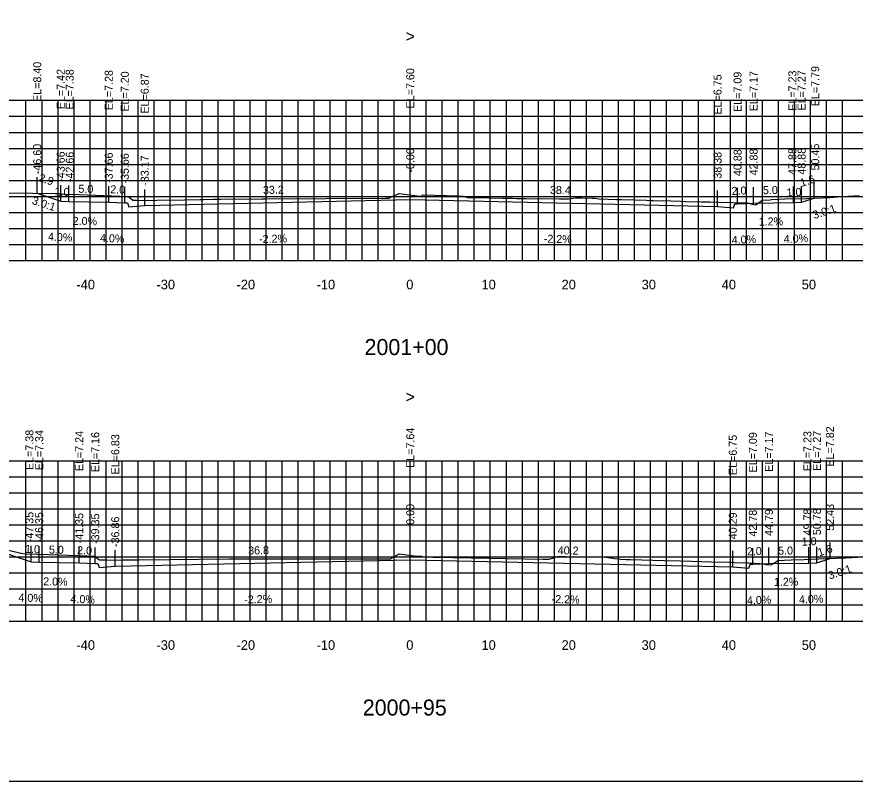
# Model space of a CAD drawing. Extents: x 1800876 to 1802446, y 250079 to 250269.
# Drawn here: x 1802241.8 to 1802346.6, y 250079.4 to 250174.9 of the extents above; entities that cross this region are included whole.
import ezdxf

# ---------------------------------------------------------------- set-up
doc = ezdxf.new("R2010")
doc.units = 0
for name, color, linetype in [('1', 7, 'Continuous'), ('10', 7, 'Continuous'), ('3', 7, 'Continuous'), ('4', 7, 'Continuous'), ('60', 7, 'Continuous'), ('CL-CNST', 7, 'Continuous'), ('Level 62', 7, 'Continuous'), ('M-ROADS', 7, 'Continuous')]:
    doc.layers.add(name, color=color, linetype=linetype)

msp = doc.modelspace()

# ---------------------------------------------------------------- linework, layer by layer
for p, q in [((1802244.4, 250152.83), (1802244.4, 250154.83)), ((1802247.34, 250151.85), (1802247.34, 250153.85)), ((1802248.34, 250151.81), (1802248.34, 250153.81)), ((1802253.34, 250151.71), (1802253.34, 250153.71)), ((1802291, 250152.03), (1802291, 250154.03)), ((1802338.88, 250151.66), (1802338.88, 250153.66)), ((1802339.88, 250151.7), (1802339.88, 250153.7)), ((1802341.46, 250152.23), (1802341.46, 250154.23)), ((1802255.34, 250151.63), (1802255.34, 250153.63)), ((1802257.83, 250151.3), (1802257.83, 250153.3)), ((1802329.38, 250151.19), (1802329.38, 250153.19)), ((1802331.88, 250151.52), (1802331.88, 250153.52)), ((1802333.88, 250151.6), (1802333.88, 250153.6)), ((1802243.65, 250106.82), (1802243.65, 250108.82)), ((1802244.65, 250106.78), (1802244.65, 250108.78)), ((1802244.65, 250106.78), (1802244.65, 250108.78)), ((1802249.65, 250106.68), (1802249.65, 250108.68)), ((1802291, 250107.07), (1802291, 250109.07)), ((1802340.78, 250106.66), (1802340.78, 250108.66)), ((1802340.79, 250106.66), (1802340.79, 250108.66)), ((1802341.78, 250106.7), (1802341.78, 250108.7)), ((1802341.79, 250106.7), (1802341.79, 250108.7)), ((1802343.43, 250107.25), (1802343.43, 250109.25)), ((1802251.65, 250106.6), (1802251.65, 250108.6)), ((1802251.65, 250106.6), (1802251.65, 250108.6)), ((1802254.14, 250106.26), (1802254.14, 250108.26)), ((1802254.15, 250106.26), (1802254.15, 250108.26)), ((1802331.29, 250106.19), (1802331.29, 250108.19)), ((1802331.29, 250106.19), (1802331.29, 250108.19)), ((1802333.78, 250106.52), (1802333.78, 250108.52)), ((1802333.79, 250106.52), (1802333.79, 250108.52)), ((1802335.78, 250106.6), (1802335.78, 250108.6)), ((1802335.79, 250106.6), (1802335.79, 250108.6))]:
    msp.add_line(p, q)
msp.add_lwpolyline([(1802141, 250079.43), (1802441, 250079.43), (1802441, 250269.43), (1802141, 250269.43)], close=True)
at = {"layer": '60'}
for p, q in [((1802141, 250144.43), (1802441, 250144.43)), ((1802251, 250144.37), (1802251, 250144.43)), ((1802261, 250144.37), (1802261, 250144.43)), ((1802271, 250144.37), (1802271, 250144.43)), ((1802281, 250144.37), (1802281, 250144.43)), ((1802291, 250144.37), (1802291, 250144.43)), ((1802301, 250144.37), (1802301, 250144.43)), ((1802311, 250144.37), (1802311, 250144.43)), ((1802321, 250144.37), (1802321, 250144.43)), ((1802331, 250144.37), (1802331, 250144.43)), ((1802341, 250144.37), (1802341, 250144.43)), ((1802141, 250099.43), (1802441, 250099.43)), ((1802251, 250099.37), (1802251, 250099.43)), ((1802261, 250099.37), (1802261, 250099.43)), ((1802271, 250099.37), (1802271, 250099.43)), ((1802281, 250099.37), (1802281, 250099.43)), ((1802291, 250099.37), (1802291, 250099.43)), ((1802301, 250099.37), (1802301, 250099.43)), ((1802311, 250099.37), (1802311, 250099.43)), ((1802321, 250099.37), (1802321, 250099.43)), ((1802331, 250099.37), (1802331, 250099.43)), ((1802341, 250099.37), (1802341, 250099.43))]:
    msp.add_line(p, q, dxfattribs=at)
at = {"layer": 'CL-CNST'}
for points in [[(1802244.4, 250152.83), (1802247.34, 250151.85), (1802248.34, 250151.81), (1802253.34, 250151.71), (1802255.34, 250151.63), (1802255.67, 250151.63), (1802255.83, 250151.13), (1802257.83, 250151.3), (1802291, 250152.03), (1802329.38, 250151.19), (1802331.38, 250151.02), (1802331.55, 250151.52), (1802331.88, 250151.52), (1802333.88, 250151.6), (1802338.88, 250151.66), (1802339.88, 250151.7), (1802341.46, 250152.23)], [(1802239.14, 250108.32), (1802243.65, 250106.82), (1802243.65, 250106.82), (1802244.65, 250106.78), (1802244.65, 250106.78), (1802249.65, 250106.68), (1802249.65, 250106.68), (1802251.65, 250106.6), (1802251.65, 250106.6), (1802251.98, 250106.6), (1802251.98, 250106.6), (1802252.15, 250106.1), (1802252.15, 250106.1), (1802254.14, 250106.26), (1802254.15, 250106.26), (1802290.99, 250107.07), (1802291, 250107.07), (1802291.04, 250107.07), (1802331.29, 250106.19), (1802331.29, 250106.19), (1802333.29, 250106.02), (1802333.29, 250106.02), (1802333.45, 250106.52), (1802333.45, 250106.52), (1802333.78, 250106.52), (1802333.79, 250106.52), (1802335.78, 250106.6), (1802335.79, 250106.6), (1802340.78, 250106.66), (1802340.79, 250106.66), (1802341.78, 250106.7), (1802341.79, 250106.7), (1802343.43, 250107.25)]]:
    msp.add_lwpolyline(points, dxfattribs=at)
at = {"layer": 'Level 62'}
for p, q in [((1802141, 250164.43), (1802441, 250164.43)), ((1802243, 250144.43), (1802243, 250164.43)), ((1802245, 250144.43), (1802245, 250164.43)), ((1802247, 250144.43), (1802247, 250164.43)), ((1802249, 250144.43), (1802249, 250164.43)), ((1802251, 250144.43), (1802251, 250164.43)), ((1802253, 250144.43), (1802253, 250164.43)), ((1802255, 250144.43), (1802255, 250164.43)), ((1802257, 250144.43), (1802257, 250164.43)), ((1802259, 250144.43), (1802259, 250164.43)), ((1802261, 250144.43), (1802261, 250164.43)), ((1802263, 250144.43), (1802263, 250164.43)), ((1802265, 250144.43), (1802265, 250164.43)), ((1802267, 250144.43), (1802267, 250164.43)), ((1802269, 250144.43), (1802269, 250164.43)), ((1802271, 250144.43), (1802271, 250164.43)), ((1802273, 250144.43), (1802273, 250164.43)), ((1802275, 250144.43), (1802275, 250164.43)), ((1802277, 250144.43), (1802277, 250164.43)), ((1802279, 250144.43), (1802279, 250164.43)), ((1802281, 250144.43), (1802281, 250164.43)), ((1802283, 250144.43), (1802283, 250164.43)), ((1802285, 250144.43), (1802285, 250164.43)), ((1802287, 250144.43), (1802287, 250164.43)), ((1802289, 250144.43), (1802289, 250164.43)), ((1802291, 250144.43), (1802291, 250164.43)), ((1802293, 250144.43), (1802293, 250164.43)), ((1802295, 250144.43), (1802295, 250164.43)), ((1802297, 250144.43), (1802297, 250164.43)), ((1802299, 250144.43), (1802299, 250164.43)), ((1802301, 250144.43), (1802301, 250164.43)), ((1802303, 250144.43), (1802303, 250164.43)), ((1802305, 250144.43), (1802305, 250164.43)), ((1802307, 250144.43), (1802307, 250164.43)), ((1802309, 250144.43), (1802309, 250164.43)), ((1802311, 250144.43), (1802311, 250164.43)), ((1802313, 250144.43), (1802313, 250164.43)), ((1802315, 250144.43), (1802315, 250164.43)), ((1802317, 250144.43), (1802317, 250164.43)), ((1802319, 250144.43), (1802319, 250164.43)), ((1802321, 250144.43), (1802321, 250164.43)), ((1802323, 250144.43), (1802323, 250164.43)), ((1802325, 250144.43), (1802325, 250164.43)), ((1802327, 250144.43), (1802327, 250164.43)), ((1802329, 250144.43), (1802329, 250164.43)), ((1802331, 250144.43), (1802331, 250164.43)), ((1802333, 250144.43), (1802333, 250164.43)), ((1802335, 250144.43), (1802335, 250164.43)), ((1802337, 250144.43), (1802337, 250164.43)), ((1802339, 250144.43), (1802339, 250164.43)), ((1802341, 250144.43), (1802341, 250164.43)), ((1802343, 250144.43), (1802343, 250164.43)), ((1802345, 250144.43), (1802345, 250164.43)), ((1802141, 250162.43), (1802441, 250162.43)), ((1802141, 250160.43), (1802441, 250160.43)), ((1802141, 250158.43), (1802441, 250158.43)), ((1802141, 250156.43), (1802441, 250156.43)), ((1802141, 250154.43), (1802441, 250154.43)), ((1802141, 250152.43), (1802441, 250152.43)), ((1802141, 250150.43), (1802441, 250150.43)), ((1802141, 250148.43), (1802441, 250148.43)), ((1802141, 250146.43), (1802441, 250146.43)), ((1802141, 250144.43), (1802441, 250144.43)), ((1802141, 250119.43), (1802441, 250119.43)), ((1802243, 250099.43), (1802243, 250119.43)), ((1802245, 250099.43), (1802245, 250119.43)), ((1802247, 250099.43), (1802247, 250119.43)), ((1802249, 250099.43), (1802249, 250119.43)), ((1802251, 250099.43), (1802251, 250119.43)), ((1802253, 250099.43), (1802253, 250119.43)), ((1802255, 250099.43), (1802255, 250119.43)), ((1802257, 250099.43), (1802257, 250119.43)), ((1802259, 250099.43), (1802259, 250119.43)), ((1802261, 250099.43), (1802261, 250119.43)), ((1802263, 250099.43), (1802263, 250119.43)), ((1802265, 250099.43), (1802265, 250119.43)), ((1802267, 250099.43), (1802267, 250119.43)), ((1802269, 250099.43), (1802269, 250119.43)), ((1802271, 250099.43), (1802271, 250119.43)), ((1802273, 250099.43), (1802273, 250119.43)), ((1802275, 250099.43), (1802275, 250119.43)), ((1802277, 250099.43), (1802277, 250119.43)), ((1802279, 250099.43), (1802279, 250119.43)), ((1802281, 250099.43), (1802281, 250119.43)), ((1802283, 250099.43), (1802283, 250119.43)), ((1802285, 250099.43), (1802285, 250119.43)), ((1802287, 250099.43), (1802287, 250119.43)), ((1802289, 250099.43), (1802289, 250119.43)), ((1802291, 250099.43), (1802291, 250119.43)), ((1802293, 250099.43), (1802293, 250119.43)), ((1802295, 250099.43), (1802295, 250119.43)), ((1802297, 250099.43), (1802297, 250119.43)), ((1802299, 250099.43), (1802299, 250119.43)), ((1802301, 250099.43), (1802301, 250119.43)), ((1802303, 250099.43), (1802303, 250119.43)), ((1802305, 250099.43), (1802305, 250119.43)), ((1802307, 250099.43), (1802307, 250119.43)), ((1802309, 250099.43), (1802309, 250119.43)), ((1802311, 250099.43), (1802311, 250119.43)), ((1802313, 250099.43), (1802313, 250119.43)), ((1802315, 250099.43), (1802315, 250119.43)), ((1802317, 250099.43), (1802317, 250119.43)), ((1802319, 250099.43), (1802319, 250119.43)), ((1802321, 250099.43), (1802321, 250119.43)), ((1802323, 250099.43), (1802323, 250119.43)), ((1802325, 250099.43), (1802325, 250119.43)), ((1802327, 250099.43), (1802327, 250119.43)), ((1802329, 250099.43), (1802329, 250119.43)), ((1802331, 250099.43), (1802331, 250119.43)), ((1802333, 250099.43), (1802333, 250119.43)), ((1802335, 250099.43), (1802335, 250119.43)), ((1802337, 250099.43), (1802337, 250119.43)), ((1802339, 250099.43), (1802339, 250119.43)), ((1802341, 250099.43), (1802341, 250119.43)), ((1802343, 250099.43), (1802343, 250119.43)), ((1802345, 250099.43), (1802345, 250119.43)), ((1802141, 250117.43), (1802441, 250117.43)), ((1802141, 250115.43), (1802441, 250115.43)), ((1802141, 250113.43), (1802441, 250113.43)), ((1802141, 250111.43), (1802441, 250111.43)), ((1802141, 250109.43), (1802441, 250109.43)), ((1802141, 250107.43), (1802441, 250107.43)), ((1802141, 250105.43), (1802441, 250105.43)), ((1802141, 250103.43), (1802441, 250103.43)), ((1802141, 250101.43), (1802441, 250101.43)), ((1802141, 250099.43), (1802441, 250099.43))]:
    msp.add_line(p, q, dxfattribs=at)
at = {"layer": 'M-ROADS'}
for points in [[(1802233.84, 250152.97), (1802247.14, 250152.8), (1802247.71, 250152.72), (1802249.61, 250152.65), (1802255.77, 250152.44), (1802255.88, 250152.35), (1802256.35, 250151.98), (1802256.82, 250151.97), (1802257.82, 250151.94), (1802259.35, 250151.97), (1802262.8, 250152.02), (1802264.76, 250152.05), (1802265.16, 250152.05), (1802266.42, 250152.07), (1802267.29, 250152.08), (1802272.41, 250152.14), (1802272.58, 250152.14), (1802272.96, 250152.14), (1802287.91, 250152.21), (1802288.31, 250152.22), (1802288.46, 250152.3), (1802289.62, 250152.78), (1802291.92, 250152.49), (1802292.36, 250152.45), (1802292.37, 250152.44), (1802292.39, 250152.42), (1802292.47, 250152.57), (1802292.52, 250152.63), (1802296.98, 250152.49), (1802297.56, 250152.47), (1802298.2, 250152.31), (1802298.54, 250152.3), (1802298.96, 250152.29), (1802299.08, 250152.28), (1802299.15, 250152.28), (1802302.54, 250152.22), (1802303.25, 250152.21), (1802303.75, 250152.2), (1802304.31, 250152.19), (1802305.49, 250152.18), (1802309.6, 250152.13), (1802310.79, 250152.12), (1802311.67, 250152.26), (1802312.01, 250152.26), (1802312.43, 250152.25), (1802313.71, 250152.23), (1802314.05, 250152.2), (1802314.07, 250152.2), (1802314.55, 250152.12), (1802316.77, 250152.06), (1802316.8, 250152.06), (1802317.25, 250152.04), (1802317.44, 250152.04), (1802320.51, 250151.95), (1802321.04, 250151.93), (1802321.34, 250151.92), (1802323.53, 250151.86), (1802324.75, 250151.82), (1802325.41, 250151.81), (1802327.36, 250151.77), (1802327.39, 250151.77), (1802328.43, 250151.74), (1802329.51, 250151.72), (1802333.13, 250151.61), (1802333.27, 250151.58), (1802333.55, 250151.51), (1802334.15, 250151.4), (1802334.62, 250151.73), (1802334.94, 250151.96), (1802335.95, 250152.02), (1802336.12, 250152.03), (1802337.78, 250152.12), (1802340.53, 250152.19), (1802343.44, 250152.31), (1802344.35, 250152.37), (1802345.69, 250152.45), (1802347.08, 250152.54)], [(1802240.49, 250108.34), (1802242.37, 250107.89), (1802242.44, 250107.89), (1802242.89, 250107.81), (1802245.9, 250107.72), (1802250.63, 250107.56), (1802251.56, 250107.53), (1802252.07, 250107.14), (1802252.16, 250107.07), (1802253.11, 250107.05), (1802254.05, 250107.04), (1802255.13, 250107.05), (1802257.14, 250107.06), (1802268.34, 250107.2), (1802269.99, 250107.2), (1802270.23, 250107.2), (1802270.64, 250107.19), (1802270.91, 250107.18), (1802271.25, 250107.18), (1802271.48, 250107.19), (1802271.78, 250107.2), (1802285.27, 250107.2), (1802286.86, 250107.19), (1802288.5, 250107.18), (1802288.52, 250107.2), (1802288.8, 250107.35), (1802289.63, 250107.82), (1802291.76, 250107.54), (1802292.46, 250107.54), (1802292.48, 250107.5), (1802292.5, 250107.45), (1802293.36, 250107.43), (1802293.86, 250107.42), (1802294.16, 250107.42), (1802307.54, 250107.16), (1802308.36, 250107.15), (1802309.01, 250107.35), (1802309.25, 250107.43), (1802309.31, 250107.45), (1802309.33, 250107.46), (1802309.35, 250107.46), (1802309.36, 250107.46), (1802309.37, 250107.47), (1802309.37, 250107.47), (1802309.4, 250107.48), (1802310.01, 250107.47), (1802310.49, 250107.47), (1802315.24, 250107.45), (1802316.51, 250107.24), (1802317.29, 250107.14), (1802317.97, 250107.12), (1802318.08, 250107.12), (1802318.14, 250107.12), (1802318.31, 250107.11), (1802318.41, 250107.11), (1802318.52, 250107.11), (1802322.72, 250107), (1802324.71, 250106.94), (1802326.13, 250106.9), (1802328.62, 250106.83), (1802330.89, 250106.76), (1802331.55, 250106.74), (1802333.18, 250106.68), (1802333.34, 250106.68), (1802334.64, 250106.63), (1802335.29, 250106.53), (1802335.47, 250106.5), (1802335.74, 250106.47), (1802336.07, 250106.44), (1802336.35, 250106.63), (1802336.9, 250106.98), (1802337.72, 250107.03), (1802338.57, 250107.05), (1802340.21, 250107.12), (1802342, 250107.19), (1802344.22, 250107.28), (1802344.78, 250107.3), (1802345.39, 250107.33), (1802346.85, 250107.42)]]:
    msp.add_lwpolyline(points, dxfattribs=at)

# ---------------------------------------------------------------- texts
for rotation, p in [(341.5651, (1802243.68, 250151.51)), (18.4349, (1802341.46, 250149.59)), (18.4345, (1802343.4, 250104.6))]:
    msp.add_text('3.0:1', height=1, rotation=rotation).set_placement(p)
at = {"layer": '1'}
for s, p in [('2001+00', (1802285.29, 250132.63)), ('2000+95', (1802285.07, 250087.63))]:
    msp.add_text(s, height=2, dxfattribs=at).set_placement(p)
at = {"layer": '10'}
for s, p in [('-40', (1802249.3, 250140.83)), ('-30', (1802259.3, 250140.83)), ('-20', (1802269.3, 250140.83)), ('-10', (1802279.3, 250140.83)), ('0', (1802290.5, 250140.83)), ('10', (1802299.9, 250140.83)), ('20', (1802309.9, 250140.83)), ('30', (1802319.9, 250140.83)), ('40', (1802329.9, 250140.83)), ('50', (1802339.9, 250140.83)), ('-40', (1802249.3, 250095.83)), ('-30', (1802259.3, 250095.83)), ('-20', (1802269.3, 250095.83)), ('-10', (1802279.3, 250095.83)), ('0', (1802290.5, 250095.83)), ('10', (1802299.9, 250095.83)), ('20', (1802309.9, 250095.83)), ('30', (1802319.9, 250095.83)), ('40', (1802329.9, 250095.83)), ('50', (1802339.9, 250095.83))]:
    msp.add_text(s, height=1.2, dxfattribs=at).set_placement(p)
at = {"layer": '3'}
for s, p in [('EL=8.40', (1802244.9, 250164.22)), ('EL=7.60', (1802291.5, 250163.42)), ('EL=7.79', (1802342.08, 250163.69)), ('EL=7.42', (1802247.84, 250163.32)), ('EL=7.38', (1802248.96, 250163.28)), ('EL=7.28', (1802253.84, 250163.18)), ('EL=7.20', (1802255.84, 250163.02)), ('EL=6.87', (1802258.33, 250162.77)), ('EL=6.75', (1802329.88, 250162.65)), ('EL=7.09', (1802332.38, 250162.98)), ('EL=7.17', (1802334.38, 250163.06)), ('EL=7.23', (1802339.23, 250163.12)), ('EL=7.27', (1802340.38, 250163.16)), ('-46.60', (1802244.9, 250155.21)), ('50.45', (1802342.08, 250155.67)), ('-43.66', (1802247.84, 250154.26)), ('-42.66', (1802248.96, 250154.22)), ('-37.66', (1802253.84, 250154.12)), ('-0.00', (1802291.5, 250155.4)), ('38.38', (1802329.88, 250154.64)), ('40.88', (1802332.38, 250154.97)), ('42.88', (1802334.38, 250155.05)), ('47.88', (1802339.23, 250155.11)), ('48.88', (1802340.38, 250155.15)), ('-35.66', (1802255.84, 250154.04)), ('-33.17', (1802258.33, 250153.76)), ('EL=7.64', (1802291.5, 250118.54)), ('EL=7.82', (1802343.93, 250118.71)), ('EL=7.38', (1802243.93, 250118.28)), ('EL=7.34', (1802245.15, 250118.24)), ('EL=7.24', (1802250.15, 250118.14)), ('EL=7.16', (1802252.15, 250118.01)), ('EL=6.83', (1802254.65, 250117.73)), ('EL=6.75', (1802331.79, 250117.65)), ('EL=7.09', (1802334.29, 250117.98)), ('EL=7.17', (1802336.29, 250118.06)), ('EL=7.23', (1802341.11, 250118.12)), ('EL=7.27', (1802342.29, 250118.16)), ('0.00', (1802291.5, 250111.44)), ('52.43', (1802343.93, 250110.7)), ('-47.35', (1802243.93, 250109.27)), ('-46.35', (1802245.15, 250109.23)), ('-41.35', (1802250.15, 250109.13)), ('40.29', (1802331.79, 250109.64)), ('42.78', (1802334.29, 250109.97)), ('44.79', (1802336.29, 250110.05)), ('49.78', (1802341.11, 250110.11)), ('50.78', (1802342.29, 250110.15)), ('-39.35', (1802252.15, 250109.05)), ('-36.86', (1802254.65, 250108.67))]:
    msp.add_text(s, height=1, rotation=90, dxfattribs=at).set_placement(p)
at = {"layer": '4'}
for s, rotation, p in [('2.9', 341.5651, (1802244.5, 250154.36)), ('1.6', 18.4349, (1802339.88, 250153.61)), ('5.0', 358.8542, (1802249.54, 250152.89)), ('2.0', 357.7094, (1802253.51, 250152.83)), ('33.2', 1.2603, (1802272.61, 250152.73)), ('38.4', 358.7397, (1802308.44, 250152.75)), ('2.0', 2.2906, (1802331.15, 250152.61)), ('5.0', 0.6875, (1802335.05, 250152.71)), ('1.0', 357.7094, (1802246.56, 250152.56)), ('1.0', 2.2906, (1802338.02, 250152.42)), ('2.0%', 358.8542, (1802248.82, 250148.88)), ('1.2%', 0.6875, (1802334.53, 250148.79)), ('4.0%', 357.7094, (1802245.73, 250146.92)), ('4.0%', 357.7094, (1802252.23, 250146.76)), ('-2.2%', 1.2603, (1802272.12, 250146.61)), ('-2.2%', 358.7397, (1802307.67, 250146.66)), ('4.0%', 2.2906, (1802331.17, 250146.49)), ('4.0%', 2.2906, (1802337.67, 250146.61)), ('1.0', 2.2906, (1802339.92, 250108.83)), ('1.0', 357.7093, (1802242.87, 250107.95)), ('5.0', 358.8542, (1802245.85, 250107.85)), ('2.0', 357.7093, (1802249.37, 250107.79)), ('36.8', 1.2603, (1802270.76, 250107.73)), ('40.2', 358.7397, (1802309.41, 250107.77)), ('2.0', 2.2906, (1802333.06, 250107.61)), ('5.0', 0.6875, (1802336.95, 250107.71)), ('1.6', 18.4345, (1802342.08, 250107.48)), ('2.0%', 358.8542, (1802245.14, 250103.89)), ('1.2%', 0.6875, (1802336.43, 250103.81)), ('4.0%', 357.7093, (1802242.04, 250101.88)), ('4.0%', 357.7093, (1802248.54, 250101.72)), ('-2.2%', 1.2603, (1802270.27, 250101.62)), ('-2.2%', 358.7397, (1802308.65, 250101.68)), ('4.0%', 2.2906, (1802333.07, 250101.49)), ('4.0%', 2.2906, (1802339.57, 250101.61))]:
    msp.add_text(s, height=1, rotation=rotation, dxfattribs=at).set_placement(p)
at = {"layer": '60'}
for p in [(1802290.39, 250171.68), (1802290.39, 250126.67)]:
    msp.add_text('>', height=1.5, dxfattribs=at).set_placement(p)

doc.saveas('drawing.dxf')
